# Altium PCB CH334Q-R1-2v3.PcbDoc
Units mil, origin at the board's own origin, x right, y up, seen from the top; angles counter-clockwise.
Board outline 3110.24 x 866.14 mil, 2 copper layers (Top Layer, Bottom Layer); 23 components, 20 nets, 131 pads, 238 vias.
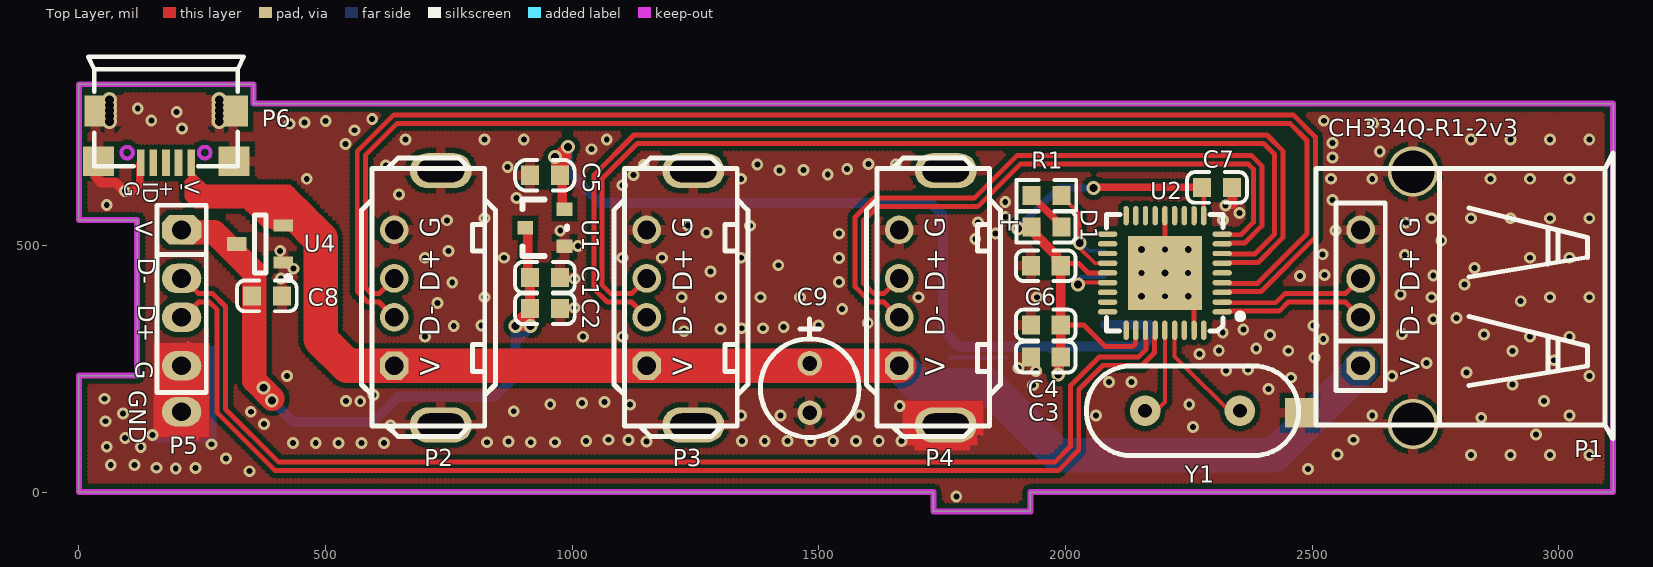
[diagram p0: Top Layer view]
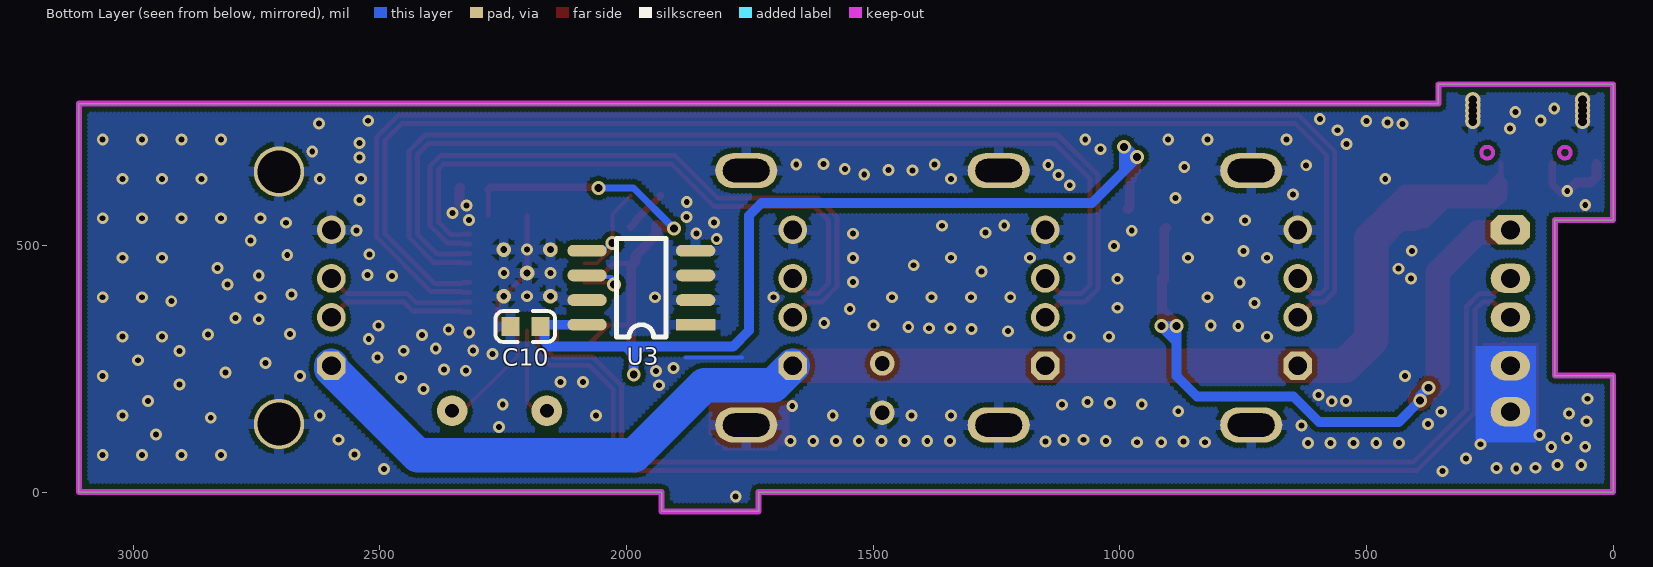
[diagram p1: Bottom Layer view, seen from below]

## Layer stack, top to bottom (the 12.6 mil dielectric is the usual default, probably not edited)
Top Solder: solder mask 0.4, Solder Resist, Dk 3.5
Top Layer: signal copper 1.4
Dielectric 1: dielectric 12.6, FR-4, Dk 4.8
Bottom Layer: signal copper 1.4
Bottom Solder: solder mask 0.4, Solder Resist, Dk 3.5

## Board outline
0,0 0,236.22 118.11,236.22 118.11,551.18 0,551.18 0,826.77 354.33,826.77 354.33,787.4 3110.24,787.4 3110.24,0 1929.13,0 1929.13,-39.37 1732.28,-39.37 1732.28,0

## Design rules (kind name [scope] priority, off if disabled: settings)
Clearance Clearance_1 [InPolygon] p1: gap=10 ignorepadtopadclearanceinfootprint=FALSE
Clearance [All] p2: gap=6 ignorepadtopadclearanceinfootprint=FALSE except(8: Arc-Via Track-Via SMDPad-Via THPad-Via Via-Via Via-Fill Via-Poly Via-Region Via-Hole)
ComponentClearance [All] p1 off: gap=10 collisioncheckmode=3 verticalgap=10 showdistances=FALSE
DiffPairsRouting [All] p1: maxlimit=10 minlimit=7 mostfreqgap=8 toplayer_minwidth=6 toplayer_maxwidth=15 toplayer_prefwidth=8 bottomlayer_minwidth=6 bottomlayer_maxwidth=15 bottomlayer_prefwidth=8 maxuncoupledlength=500
MinimumSolderMaskSliver [All] p1 off: minsoldermaskwidth=10
PolygonConnect PolygonConnect_1 [IsVia] p1: connectstyle=Direct reliefconductorwidth=10 reliefentries=4 polygonreliefangle="90 Angle" airgapwidth=10
PolygonConnect [All] p2: connectstyle=Relief reliefconductorwidth=20 reliefentries=4 polygonreliefangle="90 Angle" airgapwidth=10
RoutingVias [All] p1: holewidth=16 width=28 viastyle="Through Hole" minholewidth=12 minwidth=24 maxholewidth=28 maxwidth=50
SilkToSilkClearance [All] p1 off: silktosilkclearance=10
SilkToSolderMaskClearance [IsPad] p1 off: minsilkscreentomaskgap=10 clearancetoexposedcopper=TRUE
SolderMaskExpansion [All] p1: expansion=4 istentingtop=FALSE
Width [All] p1: maxlimit=100 minlimit=6 preferedwidth=10
25 further rules are at their usual default settings.

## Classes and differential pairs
component class CH334Q-R1-2v3: C1 C2 C5 C6 C8 C10 D1 P1 P2 P3 P4 P5 P6 R1 U2 U4 Y1
differential pair UD: +UD_p -UD_n
differential pair UD4: +UD4_p -UD4_n
differential pair UD3: +UD3_p -UD3_n
differential pair UD2: +UD2_p -UD2_n
differential pair UD1: +UD1_p -UD1_n

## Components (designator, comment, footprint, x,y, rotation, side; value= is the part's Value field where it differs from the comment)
C1 "0.1uF" 0603_C#1 914.51,435.28 r0 top
C2 "10uF" 0603_C#1 914.51,371.78 r0 top
C3 "4.7uF" 0603_C#1 1990.44,273.61 r180 top
C4 "0.1uF" 0603_C#1 1990.44,338.74 r180 top
C5 "10uF" 0603_C#2 975.14,642.25 r180 top
C6 "1uF" 0603_C#1 1929.81,458.79 r0 top
C7 "1uF" 0603_C#1 2276.9,617.52 r0 top
C8 "10uF" 0603_C#1 350.96,397.76 r0 top
C9 "220uF" CD0.1 1481.53,260.82 r270 top
C10 "NC(1uF)" 0603_C#1 2235.46,335.6 r180 bottom
D1 "LED" 0603+ 1931.19,537.14 r0 top
P1 "USB" USBAF#1 2598.25,255.91 r90 top
P2 "USB" USB2.0-A-F-TH_4P-V_13.7mm 639.21,255.91 r180 top
P3 "USB" USB2.0-A-F-TH_4P-V_13.7mm 1151.02,255.91 r180 top
P4 "USB" USB2.0-A-F-TH_4P-V_13.7mm 1662.83,255.91 r180 top
P5 "USB" USBAF#2 208.21,531.5 r270 top
P6 "PowerSupply" USBMICROB-02-GXPX-A1T2 227.66,667.45 r180 top
R1 "220Ω" 0603_R 1961.51,601.49 r180 top
U1 "6219P33M" SOT-23 984.45,498.39 r90 top
U2 "CH334Q" QFN36_6x6 2201.6,444.19 r90 top
U3 "NC(24C02)" SOIC-8_150mil 1860.04,339.22 r90 bottom
U4 "CH213K" SOT-23-3 414.47,465.45 r90 top
Y1 "12M" XT_AT49 2161.52,164.72 r270 top

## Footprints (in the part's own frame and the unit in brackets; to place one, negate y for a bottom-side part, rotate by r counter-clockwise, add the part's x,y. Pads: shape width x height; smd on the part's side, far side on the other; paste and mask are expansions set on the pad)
0603+ [mm]
  rect 0.93x0.98 smd: 1(0,0) 2(1.54,0)
  silkscreen extent -0.76,-0.79 2.27,0.79
0603_C#1 [mm]
  rect 0.93x0.98 smd: 1(0,0) 2(1.54,0)
  silkscreen extent -0.76,-0.79 2.31,0.79
0603_C#2 [mm]
  rect 0.93x0.98 smd mask+0.051: 1(0,0) 2(1.54,0)
  silkscreen extent -0.76,-0.79 2.31,0.79
0603_R [mm]
  rect 0.93x0.98 smd: 1(-0.77,0) 2(0.77,0)
  silkscreen extent -1.53,-0.79 1.54,0.79
CD0.1 [mil]
  round 50 hole 30: 1(0,0) 2(100,0)
  silkscreen extent -90,-100 150,100
QFN36_6x6 [mm]
  round 0.762 hole 0.356: 0(-1.2,-1.2) 0(-1.2,1.2) 0(0,0) 0(1.2,-1.2) 0(1.2,1.2)
  rect 3.8x3.8 smd: 0(0,0)
  oval 0.28x1 smd mask+0.051: 1(-2,-2.95) 2(-1.5,-2.95) 3(-1,-2.95) 4(-0.5,-2.95) 5(0,-2.95) 6(0.5,-2.95) 7(1,-2.95) 8(1.5,-2.95) 9(2,-2.95) 19(2,2.95) 20(1.5,2.95) 21(1,2.95) 22(0.5,2.95) 23(0,2.95) 24(-0.5,2.95) 25(-1,2.95) 26(-1.5,2.95) 27(-2,2.95)
  oval 1x0.28 smd mask+0.051: 10(2.95,-2) 11(2.95,-1.5) 12(2.95,-1) 13(2.95,-0.5) 14(2.95,0) 15(2.95,0.5) 16(2.95,1) 17(2.95,1.5) 18(2.95,2) 28(-2.95,2) 29(-2.95,1.5) 30(-2.95,1) 31(-2.95,0.5) 32(-2.95,0) 33(-2.95,-0.5) 34(-2.95,-1) 35(-2.95,-1.5) 36(-2.95,-2)
  silkscreen extent -3,-4.02 3,3
SOIC-8_150mil [mil]
  rect 24x80 smd: 1(0,0)
  oval 24x80 smd: 2(50,0) 3(100,0) 4(150,0) 5(150,220) 6(100,220) 7(50,220) 8(0,220)
  silkscreen extent -25,60 175,160
SOT-23 [mm]
  rect 0.7x0.8 smd: 1(0,0) 2(1.9,0) 3(0.95,2.02)
  silkscreen extent -0.51,-0.13 2.41,2.16
SOT-23-3 [mm] "SOT-23-3"
  rect 0.6x1 smd: 1(0,0) 2(1.9,0)
  rect 0.7x1 smd: 3(0.95,2.4)
  silkscreen extent -0.93,-0.38 2.45,1.49
USB2.0-A-F-TH_4P-V_13.7mm [mm]
  oval 3.2x1.8 hole 1.2 slot 2.4 at 0 deg: 0(-2.4,3.05) 0(-2.4,-10.05)
  oct 1.473x1.473 hole 0.965: 1(0,0)
  round 1.473 hole 0.965: 2(0,-2.5) 3(0,-4.5) 4(0,-7)
  silkscreen extent -5.21,-10.71 1.69,3.65
USBAF#1 [mm]
  round 2.6 hole 2.2: 0(-3,-2.7) 0(10,-2.7)
  oct 1.473x1.473 hole 0.965: 1(0,0)
  round 1.473 hole 0.965: 2(2.5,0) 3(4.5,0) 4(7,0)
  silkscreen extent -3.75,-12.99 10.95,2.29
USBAF#2 [mm]
  oct 1.524x2.032 hole 0.965: 1(0,0)
  oval 1.524x2.032 hole 0.965: 2(2.5,0) 3(4.5,0) 4(7,0)
  silkscreen extent -1.27,-1.27 8.38,1.27
USBMICROB-02-GXPX-A1T2 [mm]
  rect 1.6x1.5 smd: 0(-2.203,-0.083) 0(4.769,-0.083)
  rect 1.5x1.6 smd: 0(-2.167,-2.675)
  round 0.8 hole 0.45: 0(-1.442,-2.134) 0(-1.442,-3.243) 0(-1.442,-2.966) 0(-1.442,-2.689) 0(-1.442,-2.411) 0(4.208,-2.689) 0(4.208,-2.411) 0(4.208,-2.134) 0(4.208,-3.243) 0(4.208,-2.966)
  rect 1.1x1.6 smd: 0(4.933,-2.675)
  rect 0.4x1.35 smd mask+0.051: 1(0,0) 2(0.65,0) 3(1.3,0) 4(1.95,0) 5(2.6,0)
  Keep-Out Layer circle w0.203: c3.3,-0.525 r0.3
  Keep-Out Layer circle w0.203: c-0.7,-0.525 r0.3
  silkscreen extent -2.7,-5.46 5.3,0.17
XT_AT49 [mil]
  rect 60x60 smd: 0(4.07,313.9)
  round 62 hole 28: 1(0,0) 2(0,192.13)
  silkscreen extent -91,-119 91,311

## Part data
C1 C2 C3 C4 C5 C6 C7 C8 C9 C10: library part CAP, "Capacitor"
D1: "Typical INFRARED GaAs LED"
P1 P2 P3 P4 P5: "USB Port"
P6: library part MicroUSB, "MicroUSB Port"
R1: library part RES
U2: "4 ports High-Speed USB MTT Hub with over current detect & power control"
U3: library part 24C01
U4: "Ideal Diode 5V*1A"
Y1: library part XTAL, "Crystal Oscillator"

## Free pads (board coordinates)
  oval 80x60 hole 38: ""(208.21,162.81)

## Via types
v1: diameter 24, hole 12, Top Layer to Bottom Layer, tented both sides, 227 vias
v2: diameter 28, hole 16, Top Layer to Bottom Layer, tented both sides, 11 vias

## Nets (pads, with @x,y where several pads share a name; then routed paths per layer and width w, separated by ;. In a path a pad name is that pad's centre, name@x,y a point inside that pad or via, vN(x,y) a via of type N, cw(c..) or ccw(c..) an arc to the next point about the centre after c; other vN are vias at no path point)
3V3: C3.1 C4.1 C5.1 C6.2 C7.1 C10.2 D1.1 U1.2 U2.10 U2.23 U2.29 U3.8 | length 3208.8
  Top Layer w10: C4.1 2036.79,338.74 2080.55,294.98 2136.49,294.98 2142.35,300.84 2142.35,327.86 U2.29 ; C6.2@1991.69,463.31 2027.16,463.31 2046.27,444.19 U2.23 ; v2(2057.04,616.39) v2@2058.16,617.52 ; U2.10 C7.1@2280.34,614.08
  Top Layer w15: v2@2058.16,617.52 C7.1 C7.1@2280.34,614.08
  Top Layer w20: U1.2 983.6,573.19 979.82,576.97 979.82,629.7 975.14,634.38 C5.1 ; v2(1903.93,534.51) 1905.25,535.83 1929.88,535.83 D1.1 D1.1@1939.5,537.14 ; D1.1@1939.5,541.84 D1.1@1939.5,537.14 ; v2(1985.5,238.56) 1987.03,240.09 1987.03,270.19 C3.1 C4.1 1990.44,461.08 C6.2@1988.21,463.31 ; C6.2 1982.14,467.1 1982.14,478.96 1939.5,521.6 D1.1@1939.5,537.14 ; C5.1 983.45,650.56 983.45,675.14 ; C5.1 966.89,650.51 966.89,677.64 v2(965.36,679.17) 967.52,679.17 986.72,698.37 987.97,698.37 988.44,697.9 988.44,680.13 983.45,675.14 ; C5.1 975.14,666.94 975.25,666.94 983.45,675.14
  Bottom Layer w15: v2(1903.93,534.51) 1985.81,616.39 v2(2057.04,616.39)
  Bottom Layer w20: v2(1985.5,238.56) 1985.5,278.1 ; U3.8 2171.21,339.22 C10.2 2166.52,327.29 2166.52,306.78 2154.8,295.06 2002.46,295.06 ; v2@965.36,677.01 965.99,677.64 989.21,677.64 991.44,675.41 ; v2@965.36,677.01 v2(965.36,679.17) 967.52,679.17 986.72,698.37 989.91,698.37 v2(991.44,699.9) 991.44,675.41 ; v2@965.36,677.01 991.44,650.93 ; 991.44,650.93 1056.65,585.72 1726.3,585.72 1751.53,560.48 1751.53,327.3 1783.77,295.06 1969.07,295.06 ; 991.44,650.93 991.44,675.41 ; 1969.07,295.06 2002.46,295.06 ; 1969.07,295.06 1985.5,278.64 1985.5,278.1 ; 1985.5,278.1 2002.46,295.06
5V: C1.1 C2.1 C8.1 P5.1 U1.3 U4.3 | length 1543.1
  Top Layer w20: v2(374.39,211.44) 378.76,211.44 v2@381.88,214.56 ; U1.3 906.08,535.79 909.86,532.01 C1.1@909.86,439.93 ; C1.1@909.86,429.64 C1.1@909.86,439.93 ; 915.69,403.61 915.56,403.73 914.51,403.73 ; 894.36,350.65 914.51,370.8 C2.1 ; 894.36,350.65 886.83,343.12 886.83,338.4 v2(885.3,336.86) 885.43,336.73 v2@913.4,336.73 ; 894.36,350.65 899.48,350.65 v2@913.4,336.73 ; C1.1@909.86,439.93 C1.1 914.51,403.73 ; v2@913.4,336.73 913.53,336.61 v2(915.69,336.61) v2@915.1,337.2 ; v2@913.4,336.73 914.64,336.73 v2@915.1,337.2 ; C2.1 915.1,371.19 v2@915.1,337.2 ; C2.1 914.51,403.73
  Top Layer w50: P5.1 212.86,526.85 274.7,526.85 355.63,445.93 355.63,226.31 v2@392.22,189.72
  Bottom Layer w20: v2(374.39,211.44) 391.13,194.69 v2(391.13,185.56) 434.49,142.21 596.26,142.21 647.83,193.78 843.88,193.78 885.3,235.2 885.3,304.78 ; 885.3,304.78 915.69,335.17 v2(915.69,336.61) 915.56,336.73 885.43,336.73 v2(885.3,336.86) 885.3,304.78
GND: C1.2 C2.2 C3.2 C4.2 C5.2 C6.1 C7.2 C8.2 C9.2 C10.1 P1.0 P1.4 P2.0 P2.4 P3.0 P3.4 P4.0 P4.4 P5.4 P6.0 P6.5 pad. U1.1 U2.0 U2.14 U2.35 U3.1 U3.2 U3.3 U3.4 U3.7 U4.1 Y1.0 | length 1416.6
  Top Layer w8: 220.81,208.41 220.81,302.53 ; 222,112.53 222,206.65 ; 225,112.53 225,206.65 ; 227.09,204.87 227.09,299 ; 230,111.08 230,205.21 ; 233,204.17 233,298.3 ; 234,111.08 234,205.21 ; 240,107.99 240,295.21
  Top Layer w10: U2.14 v1(2201.6,491.44) 2201.6,444.19 2248.84,396.95 2260.65,385.14 U2.35
  Top Layer w15: 104.84,605.5 123.71,624.36 P6.5@123.71,665.85
  Top Layer w20: P6.0@33.46,665 33.46,639.41 45.12,627.76 74.35,627.76 91.94,610.17 v1(93.02,610.17) ; C7.2 2338.91,616.14 2338.91,584
  Bottom Layer w8: 1766,273 1880.24,273
  other v1: 1778.73,-8.71 345.77,42.29 2491.95,46.89 196.36,47.86 157.58,49.29 236.59,48.81 64.67,55.04 112.56,54.56 298,68.06 2822,75 2902,75 2982,75 3062,75 2551.51,75.81 125.49,91.43 56.53,91.91 269.09,96.97 433.87,99.3 480.12,99.3 526.37,99.3 572.62,99.3 618.87,99.3 827.57,100.97 916.07,100.97 965.42,100.97 870.97,102.68 1150.93,102.68 1344.12,103.19 1390.38,103.19 1436.63,103.19 1482.89,103.19 1529.14,103.19 1575.4,103.19 1621.65,103.19 1667.91,103.19 1028.39,103.53 1114.34,105.23 1073.49,106.08 2584.23,106.08 93.89,109.63 149.43,115.38 2953.66,116.98 2258.89,131.96 631.58,135.1 375.22,137.9 54.14,143.63 2842.89,150.73 1342,155 1422,155 1582,155 2062,155 2622,155 3022,155 89.58,159.43 348.54,162.86 881.63,163.78 1664.05,174.13 1117.55,177.16 955.63,177.89 2251.01,177.75 1020.11,180.82 1065.53,182.28 541.55,184.27 570.41,184 2970.04,184.47 51.74,189.12 597.4,196.82 2411.38,208.8 1934.38,216.53 2906.47,218.22 2088.15,223.28 2133.56,223.42 2457.36,231.79 422,235 2662,235 3062,235 2813.04,242.58 1940.27,245.55 2325.88,246.03 2370.15,248.44 1905.12,251.29 2732.05,261.79 2990.27,267.24 2504.94,273.06 2271.56,280.21 2451.81,286.5 2906.47,285.71 2310.89,287.24 2386.8,291.25 2522.53,310.02 702,315 1022,315 1102,315 2942,315 3022,315 2414.37,318.61 2848.67,319.45 2681.97,320.55 2318.85,323.76 1226.76,326.1 2360.52,329.85 1300.83,330.59 1343.48,332.09 1386.87,332.09 1428.77,334.33 760.01,336.88 2502.56,337.28 815.69,337.61 1499.1,338.07 1599.31,342.91 2745.54,350.41 2792.74,353.2 1547.41,370.82 1004.45,373.56 727.04,383.04 2922.84,386.94 822,395 1222,395 1302,395 1382,395 1462,395 1702,395 1942,395 2742,395 2982,395 3062,395 2201.6,396.95 2679.08,400.49 2809.11,420.69 756.97,424.97 1540.89,425.93 1004.9,432.32 409.76,433.09 2475.79,437.69 2745.54,439.02 2525.06,439.95 2154.35,444.19 2248.84,444.19 1280.14,447.3 434.85,452.84 2829.34,454.43 1417.86,459.82 702,475 862,475 1102,475 1182,475 1342,475 1540.89,474.84 2942,475 3022,475 2687.75,480.44 2521.44,481.99 408.11,489.06 749.2,488.72 1011.71,499.02 2761.91,510.3 1817.23,512.68 1540.89,523.74 1858.61,524.07 1272.17,525.84 975.86,529.87 2547.29,530.47 1234.39,540.41 1360.82,539.86 2690.64,545.94 1822.68,546.71 746.09,550.91 2319.16,551.7 822,555 2742,555 2822,555 2902,555 2982,555 3062,555 1878.69,557.77 2352.83,565.88 2324.47,580.77 56.52,582.14 1878.01,587.76 2541.58,592.37 887.15,596.12 648.72,602.95 1101.53,621.94 462,635 1342,635 2538.39,635.16 2622,635 2862,635 2942,635 3022,635 1124.58,642.66 1518.12,643.48 1420.29,652.29 1468.97,653.22 1557.53,654.61 869.27,658.64 622.24,662.42 1145.12,662.73 1375.3,663.89 1655.97,663.89 1600.66,664.72 2541.34,678.13 2637.09,690.68 1039.31,695.09 540.34,705.78 2541.34,707.82 662,715 822,715 902,715 1070.19,714.85 2822,715 2902,715 2982,715 3062,715 559.03,733.42 209.17,737.14 426.68,746.52 2623.79,747.43 457.39,749.48 500.31,752.44 146.87,753.14 2523.77,752.66 594.56,756.21 198.29,770.28 119.32,777.75
NetD1_2: D1.2 R1.2 | length 89.5
  Top Layer w15: R1.2 1931.19,600.51 1981.01,550.69 1981.01,547.95 D1.2
NetU2_32: U2.32 Y1.1 | length 201.9
  Top Layer w8: Y1.1@2161.52,142.72 2201.6,182.8 U2.32
NetU2_33: U2.33 Y1.2 | length 240.2
  Top Layer w8: U2.33 2221.28,275.09 Y1.2@2353.65,142.72
RST: U2.26
SCL: U2.24 U3.6 | length 130.4
  Top Layer w8: v2(2025.56,420.6) 2030.97,420.6 2035.39,425.02 2084.95,425.02 U2.24
  Bottom Layer w8: v2(2025.56,420.6) 2025.56,431.29 2030.42,436.16 2076.98,436.16 U3.6
SDA: R1.1 U2.22 U3.5 | length 245.1
  Top Layer w8: R1.1 1991.82,600.51 2028.9,563.43 v2(2028.9,504.62) 2028.9,494.79 2059.81,463.88 U2.22
  Bottom Layer w8: v2@2032.77,504.62 2048.17,489.22 U3.5
UD1_n: P1.2 U2.1 | length 301.5
  Top Layer w10: U2.1 2318.23,365.45 2332.19,365.45 2333.53,366.8 2433.42,366.8 2451.82,385.2 2567.38,385.2 P1.2
UD1_p: P1.3 U2.2 | length 301.5
  Top Layer w10: U2.2 2332.19,385.14 2333.53,383.8 2426.37,383.8 2444.78,402.2 2567.38,402.2 P1.3
UD2_n: P2.2 U2.3 | length 2810.6
  Top Layer w10: P2.2 608.34,385.2 585.78,385.2 564.28,406.71 564.28,690.57 638.25,764.54 2461.92,764.54 2506.68,719.78 2506.68,516.39 2396.46,406.17 2333.53,406.17 2332.19,404.82 U2.3
UD2_p: P2.3 U2.4 | length 2698
  Top Layer w10: P2.3 608.34,402.2 592.82,402.2 581.28,413.75 581.28,683.53 645.29,747.54 2454.88,747.54 2489.68,712.74 2489.68,523.43 2389.42,423.17 2333.53,423.17 2332.19,424.51 U2.4
UD3_n: P3.2 U2.6 | length 2125.8
  Top Layer w10: P3.2 1120.15,385.2 1071.13,385.2 1043.9,412.43 1043.9,642.56 1125.3,723.96 2408.54,723.96 2440.8,691.71 2440.8,515.73 2390.29,465.22 2333.53,465.22 2332.19,463.88 U2.6
UD3_p: P3.3 U2.7 | length 2013.1
  Top Layer w10: P3.3 1120.15,402.2 1078.17,402.2 1060.9,419.47 1060.9,635.52 1132.34,706.96 2401.5,706.96 2423.8,684.66 2423.8,522.77 2383.25,482.22 2333.53,482.22 2332.19,483.56 U2.7
UD4_n: P4.2 U2.8 | length 1357.7
  Top Layer w10: P4.2 1631.96,385.2 1604.56,385.2 1573.7,416.07 1573.7,557.53 1611.91,595.75 1815.14,595.75 1901.27,681.88 2377.68,681.88 2398.03,661.53 2398.03,539.58 2363.04,504.59 2333.53,504.59 2332.19,503.25 U2.8
UD4_p: P4.3 U2.9 | length 1245.1
  Top Layer w10: P4.3 1631.96,402.2 1611.6,402.2 1590.7,423.11 1590.7,550.49 1618.95,578.75 1822.18,578.75 1908.32,664.88 2370.64,664.88 2381.03,654.49 2381.03,546.62 2355.99,521.59 2333.53,521.59 2332.19,522.93 U2.9
UD_n: P5.2 U2.30 | length 2437.5
  Top Layer w10: P5.2 211.83,433.07 242.7,402.2 271.31,402.2 297.25,376.26 297.25,168.13 404.84,60.54 1978.19,60.54 2009.94,92.3 2009.94,215.01 2068.97,274.04 2148.23,274.04 2163.57,289.38 2163.57,312.26 2162.23,313.6 U2.30
UD_p: P5.3 U2.31 | length 2465.6
  Top Layer w10: P5.3 211.83,354.33 242.7,385.2 264.27,385.2 280.25,369.22 280.25,161.09 397.8,43.54 1841.63,43.54 1985.23,43.54 2026.94,85.26 2026.94,207.97 2076.01,257.04 2155.27,257.04 2180.57,282.34 2180.57,312.26 2181.91,313.6 U2.31
VBUS: C9.1 P1.1 P2.1 P3.1 P4.1 P6.1 U4.2 | length 4798.6
  Top Layer w10: 247.13,591.38 252.13,591.38 ; 252.85,603.63 251.45,605.02 ; 252.85,608.63 252.85,605.02 ; 254.37,584.14 259.37,584.14 ; 387.32,566.26 385.68,567.9 348.81,567.9 ; 391.02,551.74 389.8,552.95 363.76,552.95 ; 392.44,572.81 389.38,575.87 340.84,575.87 ; 394.44,555.44 389.52,560.35 356.36,560.35 ; U4.2 376.46,540.26 363.76,552.95 ; 426.32,575.65 417.83,584.14 259.37,584.14 ; 454.51,586.47 449.6,591.38 266.49,591.38 ; 475.58,570.24 432.72,613.1 432.44,613.1 ; 476.72,568.53 440.23,605.02 269.41,605.02 ; 477.29,568.25 432.44,613.1 ; 479.85,564.55 444.38,600.02 274.41,600.02 ; 219.15,602.21 241.73,579.63 ; 219.15,602.21 219.15,629.22 226.76,636.83 226.76,666.54 P6.1 P6.1@227.66,646.78 ; 219.15,602.21 219.15,597.21 236.73,579.63 241.73,579.63 ; 227.66,610.85 227.66,604.47 252.5,579.63 ; 227.66,610.85 227.66,619.83 ; 227.66,610.85 227.66,615.85 238.49,605.02 ; 227.66,619.83 227.66,628.81 ; 227.66,619.83 242.47,605.02 ; 227.66,628.81 251.45,605.02 ; 227.66,628.81 P6.1@227.66,646.78 ; P6.1@227.66,646.78 234.14,640.3 ; 234.14,640.3 255.64,618.8 ; 234.14,640.3 234.14,633.09 262.21,605.02 ; 238.49,605.02 242.47,605.02 ; 238.49,605.02 252.13,591.38 ; 241.73,579.63 252.5,579.63 ; 242.47,605.02 251.45,605.02 ; 242.47,605.02 247.47,600.02 257.85,600.02 ; 251.45,605.02 252.85,605.02 ; 252.13,591.38 266.49,591.38 ; 252.13,591.38 259.37,584.14 ; 252.5,579.63 263.88,579.63 ; 252.85,605.02 262.21,605.02 ; 252.85,605.02 257.85,600.02 ; 255.64,618.8 261.34,613.1 ; 255.64,618.8 426.74,618.8 432.44,613.1 ; 257.85,600.02 267.21,600.02 ; 257.85,600.02 266.49,591.38 ; 259.37,584.14 263.88,579.63 ; 261.34,613.1 432.44,613.1 ; 261.34,613.1 269.41,605.02 ; 262.21,605.02 269.41,605.02 ; 262.21,605.02 267.21,600.02 ; 263.88,579.63 337.09,579.63 340.84,575.87 ; 267.21,600.02 274.41,600.02 ; 269.41,605.02 274.41,600.02 ; 340.84,575.87 348.81,567.9 ; 348.81,567.9 356.36,560.35 ; 356.36,560.35 363.76,552.95
  Top Layer w70: 405.69,564.51 438.39,564.51 489.85,513.05 489.85,310.22 544.16,255.91 P2.1 P3.1 P4.1
  Bottom Layer w70: P4.1 1702.3,216.44 1842.4,216.44 1984.38,74.46 2423.1,74.46 2598.25,249.61 P1.1
pads on no net: P6.2 P6.3 P6.4 U2.5 U2.11 U2.12 U2.13 U2.15 U2.16 U2.17 U2.18 U2.19 U2.20 U2.21 U2.25 U2.27 U2.28 U2.34 U2.36

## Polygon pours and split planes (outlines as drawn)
GND on Top Layer "GND" (hatched 90Degree grid 8 track 8, remove dead copper, pour order 0): 0,826.77 0,551.18 118.11,551.18 118.11,236.22 0,236.22 0,0 1732.28,0 1732.28,-39.37 1929.13,-39.37 1929.13,0 3110.24,0 3110.24,787.4 354.33,787.4 354.33,826.77
GND on Bottom Layer "GND" (hatched 90Degree grid 8 track 8, remove dead copper, pour order 1): 0,826.77 0,551.18 118.11,551.18 118.11,236.22 0,236.22 0,0 1732.28,0 1732.28,-39.37 1929.13,-39.37 1929.13,0 3110.24,0 3110.24,787.4 354.33,787.4 354.33,826.77

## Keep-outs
Keep-Out Layer:
  the board outline again, w12

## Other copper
Top Layer:
  rectangle net GND: 1694,84.44 1806,101.7
  rectangle net GND: 1668.7,94.34 1822.2,119.41
  rectangle net GND: 1669.7,115 1834.11,185.26
  rectangle net GND: 151.31,111.08 265.24,302.38
Bottom Layer:
  rectangle net GND: 156.56,100.86 278.7,295.9

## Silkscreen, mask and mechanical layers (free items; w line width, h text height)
Top Overlay:
  text "CH334Q-R1-2v3" at 2532.39,721.18 h35
  text "GND" at 102.23,206.83 h35 r270
Mechanical 1:
  lines w10: 0,0 0,236.22 118.11,236.22 118.11,551.18 0,551.18 0,787.4 0,826.77 354.33,826.77 354.33,787.4 3110.24,787.4 3110.24,0 1929.13,0 1929.13,-39.37 1732.28,-39.37 1732.28,0 0,0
